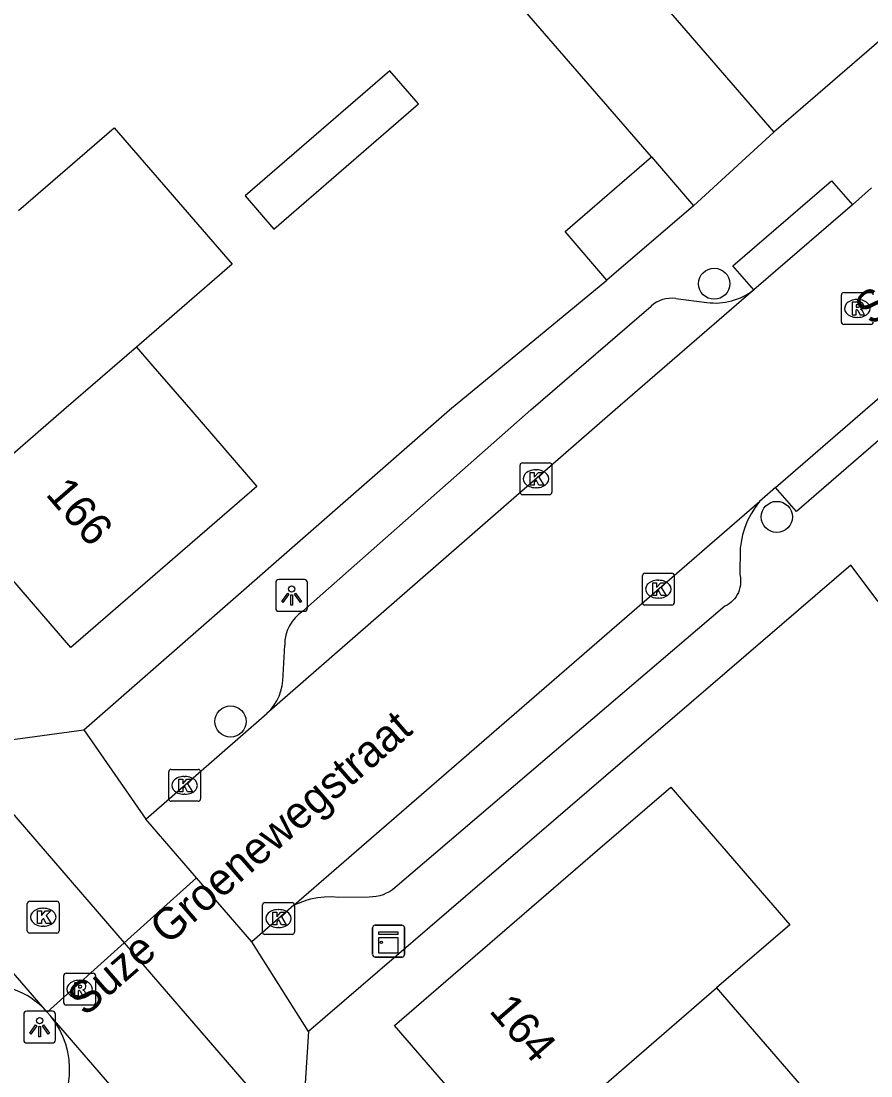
# Model space of a CAD drawing. Extents: x 160304 to 160954, y 383686 to 384161.
# Drawn here: x 160416.53 to 160443.23, y 383979.08 to 384012.21 of the extents above; entities that cross this region are included whole.
import ezdxf

# ---------------------------------------------------------------- set-up
doc = ezdxf.new("R2010")
doc.units = 0
for name, color, linetype in [('IMGEO_Boom', 7, 'Continuous'), ('IMGEO_Kast', 7, 'Continuous'), ('IMGEO_Kolk', 7, 'Continuous'), ('IMGEO_Lichtpunt', 7, 'Continuous'), ('IMGEO_Openbare_ruimte_label', 7, 'Continuous'), ('IMGEO_Pand', 7, 'Continuous'), ('IMGEO_Pand_nummerreeks', 7, 'Continuous'), ('IMGEO_Rijbaan_lokaal_open', 7, 'Continuous'), ('IMGEO_Rioolput', 7, 'Continuous'), ('IMGEO_Voetpad_open', 7, 'Continuous')]:
    doc.layers.add(name, color=color, linetype=linetype)

msp = doc.modelspace()

# ---------------------------------------------------------------- linework, layer by layer
at = {"layer": 'IMGEO_Boom'}
for centre in [(160438.303, 384003.964), (160440.269, 383996.639), (160423.109, 383990.215)]:
    msp.add_circle(centre, 0.489, dxfattribs=at)
at = {"layer": 'IMGEO_Kast'}
for p, q in [((160427.571, 383982.89), (160427.571, 383983.731)), ((160427.571, 383983.731), (160427.571, 383982.89)), ((160427.646, 383983.815), (160428.487, 383983.815)), ((160428.487, 383983.815), (160427.646, 383983.815)), ((160428.571, 383983.74), (160428.571, 383982.899)), ((160428.571, 383982.899), (160428.571, 383983.74)), ((160428.496, 383982.815), (160427.655, 383982.815)), ((160427.655, 383982.815), (160428.496, 383982.815))]:
    msp.add_line(p, q, dxfattribs=at)
for points in [[(160427.766, 383983.605), (160428.366, 383983.605), (160428.366, 383983.52), (160427.766, 383983.52), (160427.766, 383983.605)], [(160427.766, 383983.43), (160428.366, 383983.43), (160428.366, 383982.941), (160427.766, 383982.941), (160427.766, 383983.43)]]:
    msp.add_lwpolyline(points, dxfattribs=at)
msp.add_circle((160427.85, 383983.279), 0.0377, dxfattribs=at)
for centre, start, end in [((160427.649, 383983.737), 92.4484, 184.2845), ((160427.649, 383983.737), 92.4484, 184.2845), ((160428.493, 383983.737), 2.4484, 94.2845), ((160428.493, 383983.737), 2.4484, 94.2845), ((160427.649, 383982.893), 182.4484, 274.2845), ((160427.649, 383982.893), 182.4484, 274.2845), ((160428.493, 383982.893), 272.4484, 4.2845), ((160428.493, 383982.893), 272.4484, 4.2845)]:
    msp.add_arc(centre, 0.0779, start, end, dxfattribs=at)
at = {"layer": 'IMGEO_Kolk'}
for p, q in [((160432.28, 383998.337), (160433.132, 383998.337)), ((160432.205, 383997.411), (160432.205, 383998.263)), ((160432.693, 383998.117), (160432.718, 383998.117)), ((160433.206, 383998.263), (160433.206, 383997.411)), ((160433.132, 383997.337), (160432.28, 383997.337)), ((160432.716, 383997.557), (160432.691, 383997.557)), ((160436.049, 383993.944), (160436.049, 383994.796)), ((160436.124, 383994.87), (160436.976, 383994.87)), ((160436.537, 383994.65), (160436.562, 383994.65)), ((160437.05, 383994.796), (160437.05, 383993.944)), ((160436.56, 383994.09), (160436.535, 383994.09)), ((160436.976, 383993.87), (160436.124, 383993.87)), ((160421.242, 383988.707), (160422.094, 383988.707)), ((160421.167, 383987.781), (160421.167, 383988.633)), ((160421.655, 383988.487), (160421.68, 383988.487)), ((160422.168, 383988.633), (160422.168, 383987.781)), ((160422.094, 383987.707), (160421.242, 383987.707)), ((160421.678, 383987.927), (160421.653, 383987.927)), ((160416.726, 383983.64), (160416.726, 383984.492)), ((160416.801, 383984.566), (160417.653, 383984.566)), ((160417.727, 383984.492), (160417.727, 383983.64)), ((160424.116, 383983.599), (160424.116, 383984.451)), ((160424.191, 383984.525), (160425.043, 383984.525)), ((160425.117, 383984.451), (160425.117, 383983.599)), ((160417.214, 383984.346), (160417.239, 383984.346)), ((160424.604, 383984.305), (160424.629, 383984.305)), ((160417.237, 383983.786), (160417.212, 383983.786)), ((160424.627, 383983.745), (160424.602, 383983.745)), ((160417.653, 383983.566), (160416.801, 383983.566)), ((160425.043, 383983.525), (160424.191, 383983.525))]:
    msp.add_line(p, q, dxfattribs=at)
for points in [[(160432.28, 383998.337), (160433.132, 383998.337)], [(160432.205, 383997.411), (160432.205, 383998.263)], [(160432.526, 383998.037), (160432.649, 383998.037), (160432.649, 383997.886), (160432.779, 383998.037), (160432.943, 383998.037), (160432.797, 383997.886), (160432.95, 383997.637), (160432.798, 383997.637), (160432.713, 383997.801), (160432.649, 383997.734), (160432.649, 383997.637), (160432.526, 383997.637), (160432.526, 383998.037)], [(160433.206, 383998.263), (160433.206, 383997.411)], [(160433.132, 383997.337), (160432.28, 383997.337)], [(160436.049, 383993.944), (160436.049, 383994.796)], [(160436.124, 383994.87), (160436.976, 383994.87)], [(160437.05, 383994.796), (160437.05, 383993.944)], [(160436.37, 383994.57), (160436.493, 383994.57), (160436.493, 383994.419), (160436.623, 383994.57), (160436.787, 383994.57), (160436.641, 383994.419), (160436.794, 383994.17), (160436.642, 383994.17), (160436.557, 383994.334), (160436.493, 383994.267), (160436.493, 383994.17), (160436.37, 383994.17), (160436.37, 383994.57)], [(160436.976, 383993.87), (160436.124, 383993.87)], [(160421.242, 383988.707), (160422.094, 383988.707)], [(160421.167, 383987.781), (160421.167, 383988.633)], [(160421.488, 383988.407), (160421.611, 383988.407), (160421.611, 383988.256), (160421.741, 383988.407), (160421.905, 383988.407), (160421.759, 383988.256), (160421.912, 383988.007), (160421.76, 383988.007), (160421.675, 383988.171), (160421.611, 383988.104), (160421.611, 383988.007), (160421.488, 383988.007), (160421.488, 383988.407)], [(160422.168, 383988.633), (160422.168, 383987.781)], [(160422.094, 383987.707), (160421.242, 383987.707)], [(160416.726, 383983.64), (160416.726, 383984.492)], [(160416.801, 383984.566), (160417.653, 383984.566)], [(160417.727, 383984.492), (160417.727, 383983.64)], [(160424.116, 383983.599), (160424.116, 383984.451)], [(160424.191, 383984.525), (160425.043, 383984.525)], [(160425.117, 383984.451), (160425.117, 383983.599)], [(160417.047, 383984.266), (160417.17, 383984.266), (160417.17, 383984.115), (160417.3, 383984.266), (160417.464, 383984.266), (160417.318, 383984.115), (160417.471, 383983.866), (160417.319, 383983.866), (160417.234, 383984.03), (160417.17, 383983.963), (160417.17, 383983.866), (160417.047, 383983.866), (160417.047, 383984.266)], [(160424.437, 383984.225), (160424.56, 383984.225), (160424.56, 383984.074), (160424.69, 383984.225), (160424.854, 383984.225), (160424.708, 383984.074), (160424.861, 383983.825), (160424.709, 383983.825), (160424.624, 383983.989), (160424.56, 383983.922), (160424.56, 383983.825), (160424.437, 383983.825), (160424.437, 383984.225)], [(160417.653, 383983.566), (160416.801, 383983.566)], [(160425.043, 383983.525), (160424.191, 383983.525)]]:
    msp.add_lwpolyline(points, dxfattribs=at)
for centre, start, end in [((160432.282, 383998.261), 91.552, 178.448), ((160432.282, 383998.261), 91.552, 178.448), ((160433.13, 383998.261), 1.552, 88.448), ((160433.13, 383998.261), 1.552, 88.448), ((160432.282, 383997.413), 181.552, 268.448), ((160432.282, 383997.413), 181.552, 268.448), ((160433.13, 383997.413), 271.552, 358.448), ((160433.13, 383997.413), 271.552, 358.448), ((160436.126, 383994.794), 91.552, 178.448), ((160436.126, 383994.794), 91.552, 178.448), ((160436.974, 383994.794), 1.552, 88.448), ((160436.974, 383994.794), 1.552, 88.448), ((160436.126, 383993.946), 181.552, 268.448), ((160436.126, 383993.946), 181.552, 268.448), ((160436.974, 383993.946), 271.552, 358.448), ((160436.974, 383993.946), 271.552, 358.448), ((160421.244, 383988.631), 91.552, 178.448), ((160421.244, 383988.631), 91.552, 178.448), ((160422.092, 383988.631), 1.552, 88.448), ((160422.092, 383988.631), 1.552, 88.448), ((160421.244, 383987.783), 181.552, 268.448), ((160421.244, 383987.783), 181.552, 268.448), ((160422.092, 383987.783), 271.552, 358.448), ((160422.092, 383987.783), 271.552, 358.448), ((160416.803, 383984.49), 91.552, 178.448), ((160416.803, 383984.49), 91.552, 178.448), ((160417.651, 383984.49), 1.552, 88.448), ((160417.651, 383984.49), 1.552, 88.448), ((160424.193, 383984.449), 91.552, 178.448), ((160424.193, 383984.449), 91.552, 178.448), ((160425.041, 383984.449), 1.552, 88.448), ((160425.041, 383984.449), 1.552, 88.448), ((160416.803, 383983.642), 181.552, 268.448), ((160416.803, 383983.642), 181.552, 268.448), ((160417.651, 383983.642), 271.552, 358.448), ((160417.651, 383983.642), 271.552, 358.448), ((160424.193, 383983.601), 181.552, 268.448), ((160424.193, 383983.601), 181.552, 268.448), ((160425.041, 383983.601), 271.552, 358.448), ((160425.041, 383983.601), 271.552, 358.448)]:
    msp.add_arc(centre, 0.0765, start, end, dxfattribs=at)
for centre, major_axis, ratio, start_param, end_param in [((160432.692, 383997.837), (-0.387, 0.002), 0.722429, 4.712389, 7.853982), ((160432.717, 383997.837), (-0.39, 0.002), 0.717154, 1.570796, 4.712389), ((160436.536, 383994.37), (-0.387, 0.002), 0.722429, 4.712389, 7.853982), ((160436.561, 383994.37), (-0.39, 0.002), 0.717154, 1.570796, 4.712389), ((160421.654, 383988.207), (-0.387, 0.002), 0.722429, 4.712389, 7.853982), ((160421.679, 383988.207), (-0.39, 0.002), 0.717154, 1.570796, 4.712389), ((160417.213, 383984.066), (-0.387, 0.002), 0.722429, 4.712389, 7.853982), ((160417.238, 383984.066), (-0.39, 0.002), 0.717154, 1.570796, 4.712389), ((160424.603, 383984.025), (-0.387, 0.002), 0.722429, 4.712389, 7.853982), ((160424.628, 383984.025), (-0.39, 0.002), 0.717154, 1.570796, 4.712389)]:
    msp.add_ellipse(centre, major_axis=major_axis, ratio=ratio, start_param=start_param, end_param=end_param, dxfattribs=at)
at = {"layer": 'IMGEO_Lichtpunt'}
for p, q in [((160425.433, 383994.672), (160424.625, 383994.672)), ((160425.433, 383994.672), (160424.625, 383994.672)), ((160424.531, 383994.577), (160424.531, 383993.77)), ((160424.531, 383994.577), (160424.531, 383993.77)), ((160425.527, 383993.77), (160425.527, 383994.577)), ((160425.527, 383993.77), (160425.527, 383994.577)), ((160424.625, 383993.676), (160425.433, 383993.676)), ((160424.625, 383993.676), (160425.433, 383993.676)), ((160417.516, 383981.114), (160416.708, 383981.114)), ((160417.516, 383981.114), (160416.708, 383981.114)), ((160416.614, 383981.019), (160416.614, 383980.212)), ((160416.614, 383981.019), (160416.614, 383980.212)), ((160417.61, 383980.212), (160417.61, 383981.019)), ((160417.61, 383980.212), (160417.61, 383981.019)), ((160416.708, 383980.118), (160417.516, 383980.118)), ((160416.708, 383980.118), (160417.516, 383980.118))]:
    msp.add_line(p, q, dxfattribs=at)
for points in [[(160424.905, 383994.241), (160424.944, 383994.213), (160424.756, 383993.951), (160424.718, 383993.978), (160424.905, 383994.241)], [(160425.007, 383994.193), (160425.054, 383994.193), (160425.054, 383993.871), (160425.007, 383993.871), (160425.007, 383994.193)], [(160425.117, 383994.213), (160425.155, 383994.24), (160425.342, 383993.978), (160425.303, 383993.95), (160425.117, 383994.213)], [(160416.988, 383980.683), (160417.027, 383980.655), (160416.839, 383980.393), (160416.801, 383980.42), (160416.988, 383980.683)], [(160417.09, 383980.635), (160417.137, 383980.635), (160417.137, 383980.313), (160417.09, 383980.313), (160417.09, 383980.635)], [(160417.2, 383980.655), (160417.238, 383980.682), (160417.425, 383980.42), (160417.386, 383980.392), (160417.2, 383980.655)]]:
    msp.add_lwpolyline(points, dxfattribs=at)
for centre in [(160425.03, 383994.375), (160417.113, 383980.817)]:
    msp.add_circle(centre, 0.0994, dxfattribs=at)
for centre, start, end in [((160424.625, 383994.577), 90, 180), ((160424.625, 383994.577), 90, 180), ((160425.433, 383994.577), 0, 90), ((160425.433, 383994.577), 0, 90), ((160424.625, 383993.77), 180, 270), ((160424.625, 383993.77), 180, 270), ((160425.433, 383993.77), 270, 0), ((160425.433, 383993.77), 270, 360), ((160416.708, 383981.019), 90, 180), ((160416.708, 383981.019), 90, 180), ((160417.516, 383981.019), 0, 90), ((160417.516, 383981.019), 0, 90), ((160416.708, 383980.212), 180, 270), ((160416.708, 383980.212), 180, 270), ((160417.516, 383980.212), 270, 0), ((160417.516, 383980.212), 270, 360)]:
    msp.add_arc(centre, 0.0946, start, end, dxfattribs=at)
at = {"layer": 'IMGEO_Pand'}
for points in [[(160424.472, 384005.679), (160429.016, 384009.609), (160428.117, 384010.649), (160423.572, 384006.719), (160424.472, 384005.679)], [(160416.449, 384006.26), (160419.459, 384008.862), (160423.166, 384004.575), (160420.156, 384001.973)], [(160434.935, 384004.073), (160433.617, 384005.604), (160436.338, 384007.945)], [(160436.338, 384007.945), (160437.655, 384006.413)], [(160437.655, 384006.413), (160434.935, 384004.073)], [(160420.156, 384001.973), (160420.671, 384001.378), (160421.862, 384000), (160423.941, 383997.595), (160418.094, 383992.539), (160414.309, 383996.917)], [(160420.156, 384001.973), (160417.874, 384000), (160414.309, 383996.917)], [(160432.006, 383976.333), (160428.265, 383980.663), (160434.642, 383986.171), (160436.938, 383988.154), (160440.676, 383983.825), (160438.37, 383981.85)], [(160432.006, 383976.333), (160438.37, 383981.85)], [(160438.37, 383981.85), (160438.564, 383981.631), (160442.108, 383977.528)]]:
    msp.add_lwpolyline(points, dxfattribs=at)
at = {"layer": 'IMGEO_Rijbaan_lokaal_open'}
for points in [[(160424.932, 384026.345), (160440.174, 384008.722)], [(160436.338, 384007.945), (160429.882, 384015.395)], [(160440.174, 384008.722), (160437.655, 384006.413)], [(160442.642, 384006.44), (160443.247, 384006.975)], [(160399.379, 384006.883), (160405.328, 384000), (160419.771, 383983.265)], [(160442.642, 384006.44), (160439.545, 384003.767)], [(160439.545, 384003.767), (160435.187, 384000), (160424.255, 383990.462)], [(160440.231, 383997.562), (160443.044, 384000), (160446.077, 384002.618)], [(160417.354, 383981.089), (160401.126, 383999.866)], [(160440.231, 383997.562), (160439.728, 383997.125)], [(160425.096, 383984.442), (160439.728, 383997.125)], [(160420.449, 383987.142), (160424.255, 383990.462)], [(160422.038, 383985.305), (160420.449, 383987.142)], [(160423.775, 383983.297), (160422.038, 383985.305)], [(160425.096, 383984.442), (160423.775, 383983.297)], [(160419.771, 383983.265), (160417.354, 383981.089)], [(160419.771, 383983.265), (160441.098, 383958.554)], [(160417.446, 383980.983), (160417.354, 383981.089)], [(160434.365, 383961.407), (160417.446, 383980.983)]]:
    msp.add_lwpolyline(points, dxfattribs=at)
at = {"layer": 'IMGEO_Rioolput'}
for p, q in [((160442.298, 384002.76), (160442.298, 384003.612)), ((160442.373, 384003.686), (160443.225, 384003.686)), ((160442.786, 384003.466), (160442.811, 384003.466)), ((160443.225, 384002.686), (160442.373, 384002.686)), ((160442.809, 384002.906), (160442.784, 384002.906)), ((160417.869, 383981.38), (160417.869, 383982.232)), ((160417.944, 383982.306), (160418.796, 383982.306)), ((160418.357, 383982.086), (160418.382, 383982.086)), ((160418.87, 383982.232), (160418.87, 383981.38)), ((160418.38, 383981.526), (160418.355, 383981.526)), ((160418.796, 383981.306), (160417.944, 383981.306))]:
    msp.add_line(p, q, dxfattribs=at)
for points in [[(160442.298, 384002.76), (160442.298, 384003.612)], [(160442.373, 384003.686), (160443.225, 384003.686)], [(160442.887, 384003.384), (160442.635, 384003.386), (160442.635, 384002.986)], [(160442.813, 384003.305), (160442.759, 384003.305), (160442.759, 384003.224)], [(160442.635, 384002.986), (160442.759, 384002.986), (160442.759, 384003.148), (160442.77, 384003.148)], [(160442.759, 384003.224), (160442.811, 384003.224)], [(160442.817, 384003.119), (160442.888, 384002.986), (160443.028, 384002.986), (160442.963, 384003.112)], [(160443.225, 384002.686), (160442.373, 384002.686)], [(160417.869, 383981.38), (160417.869, 383982.232)], [(160417.944, 383982.306), (160418.796, 383982.306)], [(160418.87, 383982.232), (160418.87, 383981.38)], [(160418.458, 383982.004), (160418.206, 383982.006), (160418.206, 383981.606)], [(160418.206, 383981.606), (160418.33, 383981.606), (160418.33, 383981.768), (160418.341, 383981.768)], [(160418.384, 383981.925), (160418.33, 383981.925), (160418.33, 383981.844)], [(160418.33, 383981.844), (160418.382, 383981.844)], [(160418.388, 383981.739), (160418.459, 383981.606), (160418.599, 383981.606), (160418.534, 383981.732)], [(160418.796, 383981.306), (160417.944, 383981.306)]]:
    msp.add_lwpolyline(points, dxfattribs=at)
for centre, radius, start, end in [((160442.375, 384003.61), 0.0765, 91.552, 178.448), ((160442.375, 384003.61), 0.0765, 91.552, 178.448), ((160443.223, 384003.61), 0.0765, 1.552, 88.448), ((160443.223, 384003.61), 0.0765, 1.552, 88.448), ((160442.819, 384003.209), 0.0964, 77.0061, 93.1865), ((160442.833, 384003.266), 0.0378, 276.6634, 79.6772), ((160442.886, 384003.274), 0.109, 350.3612, 89.416), ((160442.769, 384003.095), 0.0533, 26.0293, 88.6989), ((160442.795, 384003.413), 0.19, 274.7715, 282.9687), ((160442.884, 384003.274), 0.112, 277.5842, 350.9817), ((160442.868, 384003.059), 0.108, 29.5134, 73.7905), ((160442.375, 384002.762), 0.0765, 181.552, 268.448), ((160442.375, 384002.762), 0.0765, 181.552, 268.448), ((160443.223, 384002.762), 0.0765, 271.552, 358.448), ((160443.223, 384002.762), 0.0765, 271.552, 358.448), ((160417.946, 383982.23), 0.0765, 91.552, 178.448), ((160417.946, 383982.23), 0.0765, 91.552, 178.448), ((160418.794, 383982.23), 0.0765, 1.552, 88.448), ((160418.794, 383982.23), 0.0765, 1.552, 88.448), ((160418.34, 383981.715), 0.0533, 26.0293, 88.6989), ((160418.366, 383982.033), 0.19, 274.7715, 282.9687), ((160418.39, 383981.829), 0.0964, 77.0061, 93.1865), ((160418.404, 383981.886), 0.0378, 276.6634, 79.6772), ((160418.457, 383981.894), 0.109, 350.3612, 89.416), ((160418.455, 383981.894), 0.112, 277.5842, 350.9817), ((160418.439, 383981.679), 0.108, 29.5134, 73.7905), ((160417.946, 383981.382), 0.0765, 181.552, 268.448), ((160417.946, 383981.382), 0.0765, 181.552, 268.448), ((160418.794, 383981.382), 0.0765, 271.552, 358.448), ((160418.794, 383981.382), 0.0765, 271.552, 358.448)]:
    msp.add_arc(centre, radius, start, end, dxfattribs=at)
for centre, major_axis, ratio, start_param, end_param in [((160442.785, 384003.186), (-0.387, 0.002), 0.722429, 4.712389, 7.853982), ((160442.81, 384003.186), (-0.39, 0.002), 0.717154, 1.570796, 4.712389), ((160418.356, 383981.806), (-0.387, 0.002), 0.722429, 4.712389, 7.853982), ((160418.381, 383981.806), (-0.39, 0.002), 0.717154, 1.570796, 4.712389)]:
    msp.add_ellipse(centre, major_axis=major_axis, ratio=ratio, start_param=start_param, end_param=end_param, dxfattribs=at)
at = {"layer": 'IMGEO_Voetpad_open'}
for points in [[(160369.22, 384049.062), (160366.633, 384046.782), (160406.925, 384000), (160415.887, 383989.594), (160418.503, 383989.954)], [(160460.261, 384032.534), (160463.456, 384028.84), (160440.174, 384008.722)], [(160439.545, 384003.767), (160438.892, 384004.525), (160441.989, 384007.198), (160442.642, 384006.44)], [(160418.503, 383989.954), (160429.993, 384000), (160434.935, 384004.073)], [(160425.384, 383993.677), (160432.542, 384000), (160436.319, 384003.263)], [(160437.099, 384003.498), (160438.076, 384003.374)], [(160446.077, 384002.618), (160446.732, 384001.862), (160440.886, 383996.806), (160440.231, 383997.562)], [(160439.728, 383997.125), (160439.585, 383996.937), (160439.459, 383996.736), (160439.351, 383996.525), (160439.263, 383996.306), (160439.194, 383996.079), (160439.146, 383995.847), (160439.123, 383995.659), (160439.11, 383994.821), (160439.114, 383994.804), (160439.127, 383994.728), (160439.134, 383994.65), (160439.133, 383994.572), (160439.126, 383994.494), (160439.111, 383994.418), (160439.09, 383994.343), (160439.062, 383994.27), (160439.028, 383994.2), (160438.988, 383994.134), (160438.942, 383994.071), (160438.89, 383994.012), (160438.834, 383993.959), (160438.773, 383993.91), (160438.708, 383993.868), (160438.639, 383993.831), (160428.345, 383985.055), (160428.28, 383984.995), (160428.193, 383984.928), (160428.1, 383984.868), (160428.003, 383984.817), (160427.901, 383984.774), (160427.796, 383984.741), (160427.688, 383984.718), (160427.579, 383984.704), (160427.469, 383984.7), (160426.517, 383984.688), (160426.292, 383984.705), (160426.066, 383984.701), (160425.841, 383984.677), (160425.62, 383984.634), (160425.509, 383984.604), (160425.096, 383984.442)], [(160443.455, 383993.98), (160442.593, 383995.12), (160425.555, 383980.472)], [(160424.76, 383991.672), (160424.812, 383992.611)], [(160418.503, 383989.954), (160420.449, 383987.142)], [(160419.771, 383983.265), (160422.038, 383985.305)], [(160425.555, 383980.472), (160423.775, 383983.297)], [(160425.555, 383980.472), (160425.435, 383978.53), (160447.995, 383952.443), (160449.625, 383953.821), (160473.957, 383925.722), (160474.258, 383925.348), (160474.591, 383925.003), (160474.954, 383924.689), (160475.343, 383924.408), (160475.756, 383924.163), (160476.189, 383923.957), (160476.639, 383923.789), (160477.102, 383923.663), (160477.574, 383923.578), (160478.012, 383923.538), (160492.124, 383922.525), (160500, 383921.959), (160508.919, 383921.318), (160510.17, 383923.18), (160510.274, 383924.568)]]:
    msp.add_lwpolyline(points, dxfattribs=at)
for centre, radius, start, end in [((160438.334, 384005.353), 1.996, 262.5837, 307.3714), ((160436.971, 384002.511), 0.995, 82.6093, 130.9239), ((160426.058, 383992.629), 1.247, 122.7551, 180.8102), ((160423.149, 383991.634), 1.611, 313.3402, 1.3528), ((160415.369, 383979.283), 2.684, 42.2971, 135.319), ((160415.37, 383979.281), 2.684, 312.6828, 39.3477)]:
    msp.add_arc(centre, radius, start, end, dxfattribs=at)

# ---------------------------------------------------------------- texts
at = {"layer": 'IMGEO_Openbare_ruimte_label'}
for rotation, p in [(40.7816, (160443.263, 384002.61)), (40.9057, (160418.543, 383980.926))]:
    msp.add_text('Suze Groenewegstraat', height=1, rotation=rotation, dxfattribs=at).set_placement(p)
at = {"layer": 'IMGEO_Pand_nummerreeks'}
for s, rotation, p in [('166', 310.846, (160417.274, 383997.341)), ('164', 310.823, (160431.205, 383981.114))]:
    msp.add_text(s, height=1, rotation=rotation, dxfattribs=at).set_placement(p)

doc.saveas('drawing.dxf')
